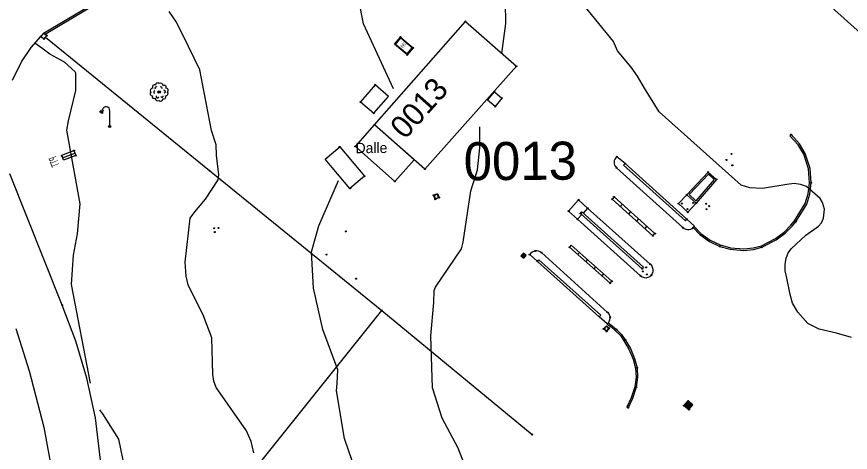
# Model space of a CAD drawing. Extents: x 344013 to 344423, y 298505 to 298795.
# Drawn here: x 344267.6 to 344347.8, y 298653.6 to 298695.5 of the extents above; entities that cross this region are included whole.
import ezdxf

# ---------------------------------------------------------------- set-up
doc = ezdxf.new("R2010")
doc.units = 0
for name, color, linetype in [('Default', 7, 'Continuous'), ('DH_CADRE -CARTOUCHE', 7, 'Continuous'), ('DH_CADRE-CARTOUCHE-NORD', 7, 'Continuous'), ('PC_CONCRETE', 7, 'Continuous'), ('PS_BOLT', 7, 'Continuous'), ('PS_CONST', 7, 'Continuous'), ('PS_DIM', 7, 'Continuous'), ('PS_HIDDEN', 7, 'Continuous'), ('PS_WELD', 7, 'Continuous'), ('RES_ELECTRICITE', 7, 'Continuous'), ('TOPO_COURBE NIVEAU', 7, 'Continuous'), ('TOPO_POINT', 7, 'Continuous'), ('VOIRIE_BORDURE', 7, 'Continuous'), ('VOIRIE_ESPACE VERT', 7, 'Continuous')]:
    doc.layers.add(name, color=color, linetype=linetype)

# ---------------------------------------------------------------- blocks, each defined once
blk = doc.blocks.new('CT2')
at = {"layer": 'Default'}
blk.add_lwpolyline([(0, 0), (1, 0), (1, 1), (0, 1)], close=True, dxfattribs=at)
blk.add_lwpolyline([(0.5, 1), (0.5, 0)], dxfattribs=at)
blk.add_text('PTT', height=0.6, dxfattribs=at).set_placement((-0.3, 1.425))
blk = doc.blocks.new('R5')
at = {"layer": 'Default'}
for p, q in [((0, 1), (0, 0)), ((1, 1), (0, 1)), ((0.2, 1), (0.2, 0)), ((0.4, 1), (0.4, 0)), ((0.6, 1), (0.6, 0)), ((0.8, 1), (0.8, 0)), ((1, 0), (1, 1)), ((0, 0), (1, 0)), ((0.6, 0), (0.6, 0))]:
    blk.add_line(p, q, dxfattribs=at)
blk = doc.blocks.new('REG_INC')
at = {"layer": 'Default'}
for p, q in [((0, 1), (1, 1)), ((0, 0), (0, 1)), ((1, 0), (0, 0)), ((1, 1), (1, 0))]:
    blk.add_line(p, q, dxfattribs=at)
for start, end in [(135.0055, 180.0055), (180.0066, 225.0066), (90.0058, 135.0058), (225.0069, 270.0069), (45.0069, 90.0069), (270.0058, 315.0058), (0.0066, 45.0066), (315.0055, 0.0055)]:
    blk.add_arc((0.5, 0.5), 0.44, start, end, dxfattribs=at)
blk = doc.blocks.new('RES_ELECTRICITE')
at = {"layer": 'RES_ELECTRICITE'}
for points in [[(0, 0), (0, 1), (1, 1), (1, 0)], [(0.05, 0.05), (0.05, 0.95), (0.95, 0.95), (0.95, 0.05)]]:
    blk.add_lwpolyline(points, close=True, dxfattribs=at)
blk.add_text('EEC', height=0.2, dxfattribs=at).set_placement((0.237, 0.46))
blk = doc.blocks.new('EDF1')
at = {"layer": 'Default'}
for points in [[(-0.855, 1.462), (-0.985, 1.373)], [(-0.83, 1.422), (-0.931, 1.303)], [(-0.793, 1.397), (-0.86, 1.257)], [(-0.753, 1.388), (-0.781, 1.235)], [(-0.701, 1.4), (-0.684, 1.241)], [(0, 0.1), (0, 1.5)]]:
    blk.add_lwpolyline(points, dxfattribs=at)
for centre, radius in [((-0.75, 1.5), 0.112), ((0, 0), 0.1)]:
    blk.add_circle(centre, radius, dxfattribs=at)
blk.add_arc((-0.35, 1.55), 0.354, 351.8699, 171.8699, dxfattribs=at)
blk = doc.blocks.new('POINT_DISPLAY')
at = {"layer": 'Default'}
blk.add_circle((0, 0), 0.05, dxfattribs=at)
blk = doc.blocks.new('ARB1')
at = {"layer": 'Default'}
blk.add_circle((0, 0), 0.122, dxfattribs=at)
for centre, radius, start, end in [((-0.153, 0.664), 0.211, 43.69255, 183.5969), ((0.139, 0.613), 0.241, 358.45835, 125.19284), ((-0.613, 0.139), 0.241, 88.45835, 215.19284), ((-0.471, 0.503), 0.183, 53.95544, 222.20655), ((-0.373, -0.024), 0.149, 103.70924, 242.34652), ((-0.276, 0.37), 0.134, 52.43963, 209.54959), ((0.164, 0.38), 0.112, 330.58954, 133.71274), ((0.501, 0.468), 0.183, 325.14445, 131.01755), ((0.458, 0.052), 0.137, 276.62143, 88.96702), ((0.613, -0.139), 0.241, 268.45835, 35.19284), ((0.664, 0.153), 0.211, 313.69255, 93.5969), ((-0.664, -0.153), 0.211, 133.69255, 273.5969), ((-0.478, -0.443), 0.19, 155.22426, 300.93774), ((-0.139, -0.613), 0.241, 178.45835, 305.19284), ((-0.163, -0.42), 0.148, 159.53711, 338.16632), ((0.153, -0.664), 0.211, 223.69255, 3.5969), ((0.271, -0.38), 0.112, 210.58954, 13.71274), ((0.448, -0.483), 0.188, 243.13234, 33.02965)]:
    blk.add_arc(centre, radius, start, end, dxfattribs=at)

msp = doc.modelspace()

# ---------------------------------------------------------------- linework, layer by layer
at = {"layer": 'DH_CADRE -CARTOUCHE'}
for points in [[(344300.695, 298736.911), (344309.284, 298729.159), (344318.375, 298721.074), (344331.766, 298709.041), (344345.307, 298697.002), (344354.351, 298688.866), (344356.37, 298691.11), (344358.623, 298689.083), (344360.288, 298690.966), (344358.051, 298692.978), (344360.392, 298695.581), (344306.859, 298743.741)], [(344270.166, 298693.919), (344269.912, 298693.596), (344270.225, 298693.35), (344270.475, 298693.676)]]:
    msp.add_lwpolyline(points, close=True, dxfattribs=at)
msp.add_lwpolyline([(344310.751, 298695.032), (344315.636, 298690.725), (344306.836, 298680.828), (344301.993, 298685.096), (344310.751, 298695.032)], dxfattribs=at)
at = {"layer": 'PS_BOLT'}
for points in [[(344302.046, 298688.946), (344300.637, 298687.299), (344301.927, 298686.208), (344303.337, 298687.808)], [(344312.868, 298687.465), (344313.543, 298688.252), (344314.249, 298687.647), (344313.591, 298686.845)], [(344298.644, 298682.955), (344301.023, 298680.138), (344299.635, 298678.976), (344297.254, 298681.796)], [(344332.041, 298678.364), (344334.093, 298680.54), (344334.882, 298679.831), (344332.917, 298677.55)], [(344332.254, 298678.371), (344334.102, 298680.33), (344334.672, 298679.817), (344332.905, 298677.766)]]:
    msp.add_lwpolyline(points, close=True, dxfattribs=at)
for points in [[(344326.092, 298681.364), (344325.313, 298682.018)], [(344325.264, 298680.952), (344331.651, 298675.204)], [(344332.917, 298677.55), (344332.136, 298676.681), (344331.244, 298677.506), (344332.041, 298678.364)], [(344328.515, 298671.676), (344322.494, 298677.06)], [(344321.528, 298676.004), (344327.581, 298670.561)], [(344332.778, 298675.336), (344332.035, 298676.006)], [(344318.059, 298672.798), (344324.409, 298667.032)], [(344317.679, 298671.946), (344316.918, 298672.607)], [(344324.359, 298665.944), (344323.615, 298666.613)]]:
    msp.add_lwpolyline(points, dxfattribs=at)
for centre, radius, start, end in [((344325.725, 298681.465), 0.69, 126.67995, 228.01267), ((344332.159, 298675.74), 0.739, 226.51554, 326.85592), ((344317.58, 298672.157), 0.801, 53.25812, 145.80344), ((344328.068, 298671.102), 0.727, 228.03851, 52.06058), ((344324.008, 298666.506), 0.662, 302.00552, 52.67765)]:
    msp.add_arc(centre, radius, start, end, dxfattribs=at)
at = {"layer": 'PS_DIM'}
for points in [[(344332.035, 298676.006), (344326.092, 298681.364), (344325.958, 298681.216), (344331.901, 298675.857)], [(344327.744, 298671.237), (344321.807, 298676.571), (344321.941, 298676.719), (344327.877, 298671.386)], [(344323.615, 298666.613), (344317.679, 298671.946), (344317.813, 298672.095), (344323.749, 298666.761)]]:
    msp.add_lwpolyline(points, close=True, dxfattribs=at)
at = {"layer": 'PS_HIDDEN'}
msp.add_lwpolyline([(344305.803, 298681.732), (344303.958, 298679.643), (344300.15, 298683.005), (344301.993, 298685.096)], close=True, dxfattribs=at)
msp.add_lwpolyline([(344321.528, 298676.004), (344320.665, 298676.789), (344321.618, 298677.855), (344322.494, 298677.06), (344322.074, 298676.6), (344321.941, 298676.719), (344321.807, 298676.571), (344321.935, 298676.456), (344321.528, 298676.004)], dxfattribs=at)
at = {"layer": 'PS_WELD'}
for points in [[(344270.35, 298693.513), (344286.12, 298680.684), (344302.703, 298667.223), (344317.17, 298655.291)], [(344276.41, 298634.41), (344289.603, 298650.85), (344302.703, 298667.223)]]:
    msp.add_lwpolyline(points, dxfattribs=at)
at = {"layer": 'TOPO_COURBE NIVEAU'}
for points in [[(344314.248, 298691.949), (344314.62, 298694.85), (344314.584, 298696.883), (344314.324, 298700.991), (344313.484, 298702.496), (344312.173, 298704.048), (344309.551, 298706.395), (344309.191, 298706.947), (344308.365, 298708.152), (344296.729, 298717.745)], [(344347.856, 298664.619), (344346.439, 298665.031), (344344.771, 298665.427), (344343.679, 298665.955), (344342.705, 298667.073), (344342.211, 298667.915), (344341.984, 298668.775), (344341.617, 298670.484), (344341.492, 298671.05), (344341.485, 298671.656), (344341.581, 298672.271), (344341.794, 298672.765), (344342.102, 298673.182), (344343.472, 298674.486), (344344.709, 298675.325), (344344.985, 298675.663), (344345.174, 298676.104), (344345.271, 298676.985), (344345.067, 298677.614), (344344.847, 298678.009), (344343.528, 298679.144), (344342.977, 298679.334), (344342.346, 298679.43), (344341.647, 298679.36), (344339.308, 298678.946), (344338.081, 298679.027), (344337.253, 298679.289), (344329.359, 298686.341), (344327.947, 298688.609), (344327.281, 298689.782), (344326.668, 298690.633), (344325.365, 298692.193), (344324.981, 298693.114), (344320.328, 298698.849)], [(344303.807, 298688.54), (344300.921, 298694.797), (344300.5, 298697.079)], [(344290.377, 298653.521), (344290.126, 298654.607), (344289.679, 298655.655), (344287.811, 298658.302), (344286.759, 298659.814), (344286.532, 298660.421), (344286.439, 298661.067), (344286.334, 298664.591), (344285.55, 298666.717), (344284.068, 298669.688), (344283.872, 298670.514), (344283.796, 298671.868), (344284.259, 298676.102), (344284.701, 298676.715), (344285.734, 298677.933), (344286.971, 298679.81), (344287.019, 298680.283), (344286.802, 298682.156), (344286.757, 298683.164), (344286.31, 298684.541), (344285.187, 298690.381), (344284.097, 298692.609), (344282.944, 298694.98), (344282.229, 298695.98)], [(344274.667, 298660.241), (344272.841, 298669.709), (344273.027, 298672.536), (344273.415, 298674.588), (344273.696, 298677.476), (344272.401, 298684.559), (344272.553, 298685.464), (344273.281, 298688.405), (344273.276, 298690.064), (344273.206, 298690.183), (344272.161, 298691.12), (344270.77, 298691.886), (344269.992, 298692.477), (344269.328, 298692.936)], [(344311.039, 298641.643), (344310.915, 298642.036), (344310.707, 298645.003), (344310.128, 298647.144), (344310.154, 298648.255), (344310.648, 298652.392), (344310.029, 298653.959), (344308.514, 298656.851), (344307.575, 298659.779), (344307.41, 298664.78), (344307.707, 298668.001), (344307.725, 298669.134), (344307.859, 298669.472), (344310.352, 298673.167), (344310.534, 298673.805), (344311.258, 298678.736), (344311.907, 298680.765), (344312.138, 298682.865), (344312.117, 298684.902)], [(344295.365, 298623.026), (344300.65, 298630.117), (344303.118, 298636.618), (344303.721, 298640.189), (344303.62, 298640.654), (344302.829, 298642.567), (344300.656, 298646.813), (344300.327, 298648.182), (344299.855, 298652.754), (344299.119, 298654.896), (344298.331, 298659.485), (344298.396, 298660.21), (344298.477, 298661.501), (344297.026, 298665.383), (344296.113, 298669.359), (344295.917, 298672.878), (344296.635, 298675.355), (344298.522, 298679.722)], [(344275.76, 298635.963), (344278.264, 298642.294), (344278.527, 298644.111), (344278.614, 298648.943), (344277.411, 298654.833), (344275.85, 298657.266), (344275.573, 298657.664)]]:
    msp.add_lwpolyline(points, dxfattribs=at)
at = {"layer": 'VOIRIE_BORDURE'}
for points in [[(344270.166, 298693.919), (344278.95, 298699.134), (344284.997, 298706.184), (344287.211, 298708.679), (344291.43, 298713.968)], [(344270.243, 298693.79), (344279.037, 298699.029), (344284.564, 298705.439), (344285.119, 298706.096), (344287.326, 298708.582), (344291.547, 298713.875)], [(344267.172, 298689.375), (344268.043, 298691.158), (344268.954, 298692.514), (344269.912, 298693.596)], [(344332.646, 298675.198), (344333.297, 298674.532), (344334.202, 298673.873), (344335.2, 298673.393), (344336.193, 298673.113), (344337.521, 298673.004), (344338.451, 298673.1), (344339.259, 298673.303), (344340.629, 298674.008), (344341.486, 298674.659), (344342.16, 298675.331), (344342.511, 298675.761), (344343.563, 298677.469), (344343.856, 298678.412), (344343.997, 298679.508), (344343.886, 298680.896), (344343.414, 298682.314), (344342.856, 298683.253), (344342.066, 298684.142)], [(344332.753, 298675.303), (344333.396, 298674.646), (344334.28, 298674.002), (344335.253, 298673.534), (344336.22, 298673.262), (344337.52, 298673.155), (344338.425, 298673.248), (344339.206, 298673.445), (344340.548, 298674.135), (344341.388, 298674.772), (344342.048, 298675.432), (344342.389, 298675.848), (344343.425, 298677.532), (344343.709, 298678.444), (344343.846, 298679.512), (344343.737, 298680.866), (344343.277, 298682.251), (344342.735, 298683.164), (344341.954, 298684.043)], [(344342.066, 298684.142), (344341.954, 298684.043)], [(344265.711, 298623.939), (344269.866, 298629.528), (344272.446, 298633.509), (344274.289, 298636.845), (344275.079, 298640.087), (344275.631, 298644.676), (344275.835, 298648.511), (344275.757, 298651.713), (344275.152, 298656.894), (344274.334, 298660.713), (344273.252, 298664.267), (344271.939, 298667.741), (344266.911, 298680.387)], [(344324.383, 298665.92), (344324.745, 298665.634), (344325.156, 298665.282), (344325.638, 298664.804), (344325.989, 298664.313), (344326.467, 298663.486), (344326.87, 298662.548), (344327.105, 298661.688), (344327.152, 298660.798), (344327.017, 298659.865), (344326.68, 298658.815), (344326.266, 298657.935)], [(344324.476, 298666.038), (344324.84, 298665.75), (344325.257, 298665.393), (344325.752, 298664.902), (344326.116, 298664.394), (344326.602, 298663.553), (344327.011, 298662.598), (344327.254, 298661.712), (344327.303, 298660.791), (344327.163, 298659.831), (344326.82, 298658.76), (344326.402, 298657.871)], [(344267.481, 298665.493), (344268.766, 298661.408), (344270.195, 298655.984), (344271.053, 298651.262), (344271.086, 298645.598), (344270.649, 298642.118), (344269.897, 298639.251), (344268.61, 298636.233), (344266.758, 298632.993)], [(344326.402, 298657.871), (344326.266, 298657.935)]]:
    msp.add_lwpolyline(points, dxfattribs=at)

# ---------------------------------------------------------------- block references
at = {"layer": 'DH_CADRE-CARTOUCHE-NORD', "xscale": 0.515137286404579, "yscale": -1.265986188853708, "rotation": -69.40719}
msp.add_blockref('CT2', (344273.089, 298682.61), dxfattribs=at)
at = {"layer": 'PC_CONCRETE'}
for name, p, xscale, yscale, rotation in [('REG_INC', (344307.842, 298677.932), 0.3981027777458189, 0.40877398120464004, 24.04061999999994), ('R5', (344324.846, 298677.923), 5.265047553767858, 0.30067286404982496, -41.81814000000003), ('R5', (344320.753, 298673.312), 5.214250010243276, 0.25022206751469, -41.571630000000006), ('REG_INC', (344316.08, 298672.495), 0.34163745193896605, -0.363553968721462, 48.11165999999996), ('REG_INC', (344324.308, 298665.209), 0.407916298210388, 0.36683430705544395, 49.101929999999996), ('R5', (344331.761, 298658.071), 0.617165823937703, 0.594766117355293, -39.01383000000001)]:
    msp.add_blockref(name, p, dxfattribs=dict(at, xscale=xscale, yscale=yscale, rotation=rotation))
at = {"layer": 'RES_ELECTRICITE', "xscale": 0.89537788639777, "yscale": 1.5906215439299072, "rotation": 49.84388999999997}
msp.add_blockref('RES_ELECTRICITE', (344305.133, 298691.819), dxfattribs=at)
at = {"layer": 'RES_ELECTRICITE'}
msp.add_blockref('EDF1', (344276.523, 298684.934), dxfattribs=at)
at = {"layer": 'TOPO_POINT'}
for p in [(344310.751, 298695.032), (344269.912, 298693.596), (344270.475, 298693.676), (344270.225, 298693.35), (344304.5, 298693.536), (344305.71, 298692.504), (344305.133, 298691.819), (344315.636, 298690.725), (344302.046, 298688.946), (344281.281, 298688.244), (344313.543, 298688.252), (344300.637, 298687.299), (344314.249, 298687.647), (344313.591, 298686.845), (344301.927, 298686.208), (344276.523, 298684.934), (344301.993, 298685.096), (344342.066, 298684.142), (344273.089, 298682.61), (344298.644, 298682.955), (344300.15, 298683.005), (344271.926, 298682.106), (344273.27, 298682.128), (344325.313, 298682.018), (344335.845, 298681.704), (344336.342, 298682.287), (344306.836, 298680.828), (344325.264, 298680.952), (344326.092, 298681.364), (344336.407, 298681.189), (344286.12, 298680.684), (344301.023, 298680.138), (344334.093, 298680.54), (344303.958, 298679.643), (344334.882, 298679.831), (344343.997, 298679.508), (344299.635, 298678.976), (344332.041, 298678.364), (344307.685, 298678.309), (344307.842, 298677.932), (344308.206, 298678.094), (344321.618, 298677.855), (344324.846, 298677.923), (344325.03, 298678.148), (344332.635, 298677.578), (344320.665, 298676.789), (344322.494, 298677.06), (344331.244, 298677.506), (344331.552, 298677.515), (344332.102, 298676.979), (344332.917, 298677.55), (344333.896, 298677.491), (344333.919, 298676.964), (344334.177, 298677.262), (344321.528, 298676.004), (344321.807, 298676.571), (344332.035, 298676.006), (344332.136, 298676.681), (344286.976, 298675.173), (344331.651, 298675.204), (344332.646, 298675.198), (344342.511, 298675.761), (344286.576, 298675.137), (344286.625, 298674.773), (344299.225, 298674.827), (344328.77, 298674.413), (344328.982, 298674.626), (344317.429, 298672.943), (344318.059, 298672.798), (344320.753, 298673.312), (344335.2, 298673.393), (344339.259, 298673.303), (344297.378, 298672.605), (344316.329, 298672.501), (344316.918, 298672.607), (344317.679, 298671.946), (344327.744, 298671.237), (344328.111, 298671.373), (344328.515, 298671.676), (344327.581, 298670.561), (344327.806, 298670.978), (344328.18, 298670.696), (344328.625, 298670.635), (344300.218, 298670.283), (344324.653, 298669.852), (344324.832, 298670.028), (344271.939, 298667.741), (344302.703, 298667.223), (344324.409, 298667.032), (344324.665, 298666.586), (344324.03, 298665.446), (344324.308, 298665.209), (344324.575, 298665.517), (344325.257, 298665.393), (344326.116, 298664.394), (344327.254, 298661.712), (344327.163, 298659.831), (344332.165, 298658.509), (344326.402, 298657.871), (344331.761, 298658.071), (344332.24, 298657.683), (344317.17, 298655.291)]:
    msp.add_blockref('POINT_DISPLAY', p, dxfattribs=at)
at = {"layer": 'VOIRIE_ESPACE VERT'}
msp.add_blockref('ARB1', (344281.281, 298688.244), dxfattribs=at)

# ---------------------------------------------------------------- texts
at = {"layer": 'PS_CONST'}
for s, height, rotation, p in [('0013', 2.1624, 48.19868, (344304.923, 298683.598)), ('Dalle', 1.0003, 0.36648, (344300.181, 298682.358)), ('0013', 3.662, 0.36647, (344310.581, 298679.747))]:
    msp.add_text(s, height=height, rotation=rotation, dxfattribs=at).set_placement(p)

doc.saveas('drawing.dxf')
